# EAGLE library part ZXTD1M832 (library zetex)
DUAL 12V PNP LOW SATURATION SWITCHING TRANSISTOR MPPS Miniature Package Power Solutions Source: www.zetex.com/ .. zxtd1m832.pdf
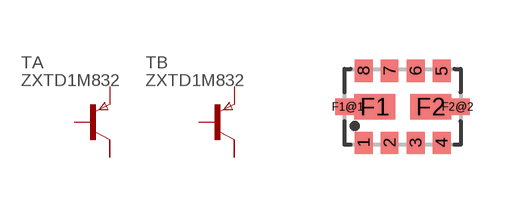
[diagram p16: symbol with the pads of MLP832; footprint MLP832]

Designator prefix T; gates A=PNP2C B=PNP2C

## ZXTD1M832 (OC_FARNELL: unknown; OC_NEWARK: unknown)  [MLP832]
1  A:B  pas
2  A:E  pas
3  B:B  pas
4  B:E  pas
5  B:C  pas
6  B:C1  pas
7  A:C  pas
8  A:C1  pas

## Footprint MLP832 (pad centres in mm)
MLP832 Package Source: www.zetex.com/ .. zxtd1m832.pdf
smd 0.44 x 0.55: 1 -0.975,-0.9; 2 -0.325,-0.9; 3 0.325,-0.9; 4 0.975,-0.9; 5 0.975,0.9; 6 0.325,0.9; 7 -0.325,0.9; 8 -0.975,0.9
smd 1.02 x 0.63: F1 -0.7,0; F2 0.7,0
smd 0.61 x 0.4: F1@1 -1.375,0; F2@2 1.375,0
